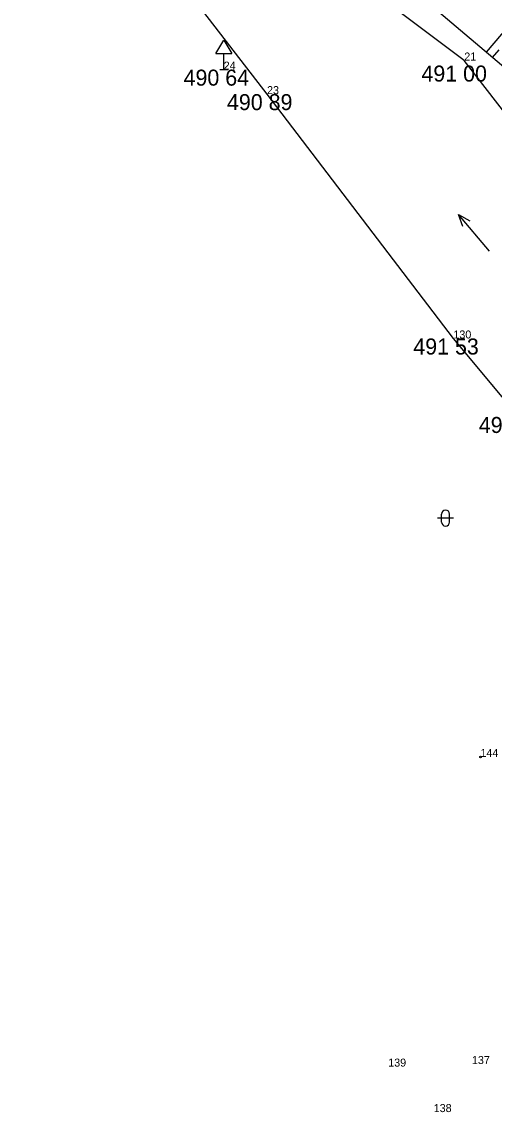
# Model space of a CAD drawing. Extents: x -559180 to -551373, y -1076947 to -1072071.
# Drawn here: x -553521.5 to -553492, y -1076655.5 to -1076587.4 of the extents above; entities that cross this region are included whole.
import ezdxf

# ---------------------------------------------------------------- set-up
doc = ezdxf.new("R2010")
doc.units = 0
for name, color, linetype in [('17_KOMUNIKACE', 7, 'Continuous'), ('1_VODA_ZN', 7, 'Continuous'), ('26_SRAFY', 7, 'Continuous'), ('27_HRANA_PATA', 7, 'Continuous'), ('3_BODY', 7, 'Continuous'), ('45_ZN_KULTURY', 7, 'Continuous'), ('48_DOPRAVA_ZN', 7, 'Continuous'), ('52_POPIS_UCELOVY', 7, 'Continuous'), ('6_VYSKY', 7, 'Continuous')]:
    doc.layers.add(name, color=color, linetype=linetype)

# ---------------------------------------------------------------- blocks, each defined once
blk = doc.blocks.new('T')
at = {"layer": '6_VYSKY'}
blk.add_circle((0, 0), 0.05, dxfattribs=at)
blk = doc.blocks.new('NEPLOD')
at = {"layer": '45_ZN_KULTURY'}
for p, q in [((0.519, 0.01), (-0.481, 0.01)), ((-0.231, -0.24), (-0.231, 0.26)), ((0.269, -0.24), (0.269, 0.26))]:
    blk.add_line(p, q, dxfattribs=at)
for centre, start, end in [((0.019, 0.26), 0, 180), ((0.019, -0.24), 180, 0)]:
    blk.add_arc(centre, 0.25, start, end, dxfattribs=at)
blk = doc.blocks.new('DZ')
at = {"layer": '48_DOPRAVA_ZN'}
for p, q in [((-0.5, 1), (0, 1.85)), ((0, 1.85), (0.5, 1)), ((-0.5, 1), (0.5, 1)), ((0, 0), (0, 1)), ((-0.25, 0), (0.25, 0))]:
    blk.add_line(p, q, dxfattribs=at)
blk = doc.blocks.new('POINT_DISPLAY')
blk.add_line((0, 0), (0, 0))
blk = doc.blocks.new('SMER')
at = {"layer": '52_POPIS_UCELOVY'}
for p, q in [((0, 0), (3, -0.001)), ((2.25, 0.28), (3, -0.001)), ((3, -0.001), (2.25, -0.281))]:
    blk.add_line(p, q, dxfattribs=at)

msp = doc.modelspace()

# ---------------------------------------------------------------- linework, layer by layer
at = {"layer": '17_KOMUNIKACE'}
for p, q in [((-553506.14, -1076591.92), (-553521.46, -1076572.08)), ((-553483.07, -1076603.71), (-553493.82, -1076589.82)), ((-553494.5, -1076607.18), (-553506.14, -1076591.92)), ((-553490.41, -1076612.08), (-553494.5, -1076607.18))]:
    msp.add_line(p, q, dxfattribs=at)
msp.add_lwpolyline([(-553493.82, -1076589.82), (-553500.742, -1076584.612), (-553502.185, -1076583.51), (-553503.96, -1076582.05)], dxfattribs=at)
at = {"layer": '26_SRAFY'}
for p, q in [((-553491.014, -1076587.612), (-553492.454, -1076589.306)), ((-553491.665, -1076589.149), (-553492.074, -1076589.63))]:
    msp.add_line(p, q, dxfattribs=at)
at = {"layer": '27_HRANA_PATA'}
msp.add_line((-553489.21, -1076592.065), (-553503.89, -1076579.58), dxfattribs=at)

# ---------------------------------------------------------------- block references
at = {"layer": '1_VODA_ZN'}
for p in [(-553508.85, -1076590.39), (-553493.82, -1076589.82), (-553506.14, -1076591.92), (-553494.5, -1076607.18), (-553491.97, -1076610.08), (-553492.81, -1076633.31)]:
    msp.add_blockref('POINT_DISPLAY', p, dxfattribs=at)
at = {"layer": '45_ZN_KULTURY'}
msp.add_blockref('NEPLOD', (-553495.013, -1076618.406), dxfattribs=at)
at = {"layer": '48_DOPRAVA_ZN'}
msp.add_blockref('DZ', (-553508.85, -1076590.39), dxfattribs=at)
at = {"layer": '52_POPIS_UCELOVY', "xscale": 1.0000024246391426, "yscale": 1.0000024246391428, "rotation": 129.99938434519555}
msp.add_blockref('SMER', (-553492.248, -1076601.728), dxfattribs=at)
at = {"layer": '6_VYSKY'}
msp.add_blockref('T', (-553492.81, -1076633.31), dxfattribs=at)
msp.add_blockref('T', (-553492.81, -1076633.31), dxfattribs=at)

# ---------------------------------------------------------------- texts
at = {"layer": '3_BODY'}
for s, p in [('21', (-553493.82, -1076589.82)), ('24', (-553508.85, -1076590.39)), ('23', (-553506.14, -1076591.92)), ('130', (-553494.5, -1076607.18)), ('144', (-553492.81, -1076633.31)), ('139', (-553498.57, -1076652.65)), ('137', (-553493.34, -1076652.49)), ('138', (-553495.73, -1076655.49))]:
    msp.add_text(s, height=0.5, dxfattribs=at).set_placement(p)
at = {"layer": '6_VYSKY'}
for s, p in [('490 64', (-553511.355, -1076591.39)), ('491 00', (-553496.497, -1076591.135)), ('490 89', (-553508.645, -1076592.92)), ('491 53', (-553497.005, -1076608.18)), ('491 73', (-553492.915, -1076613.08))]:
    msp.add_text(s, height=1, dxfattribs=at).set_placement(p)

doc.saveas('drawing.dxf')
